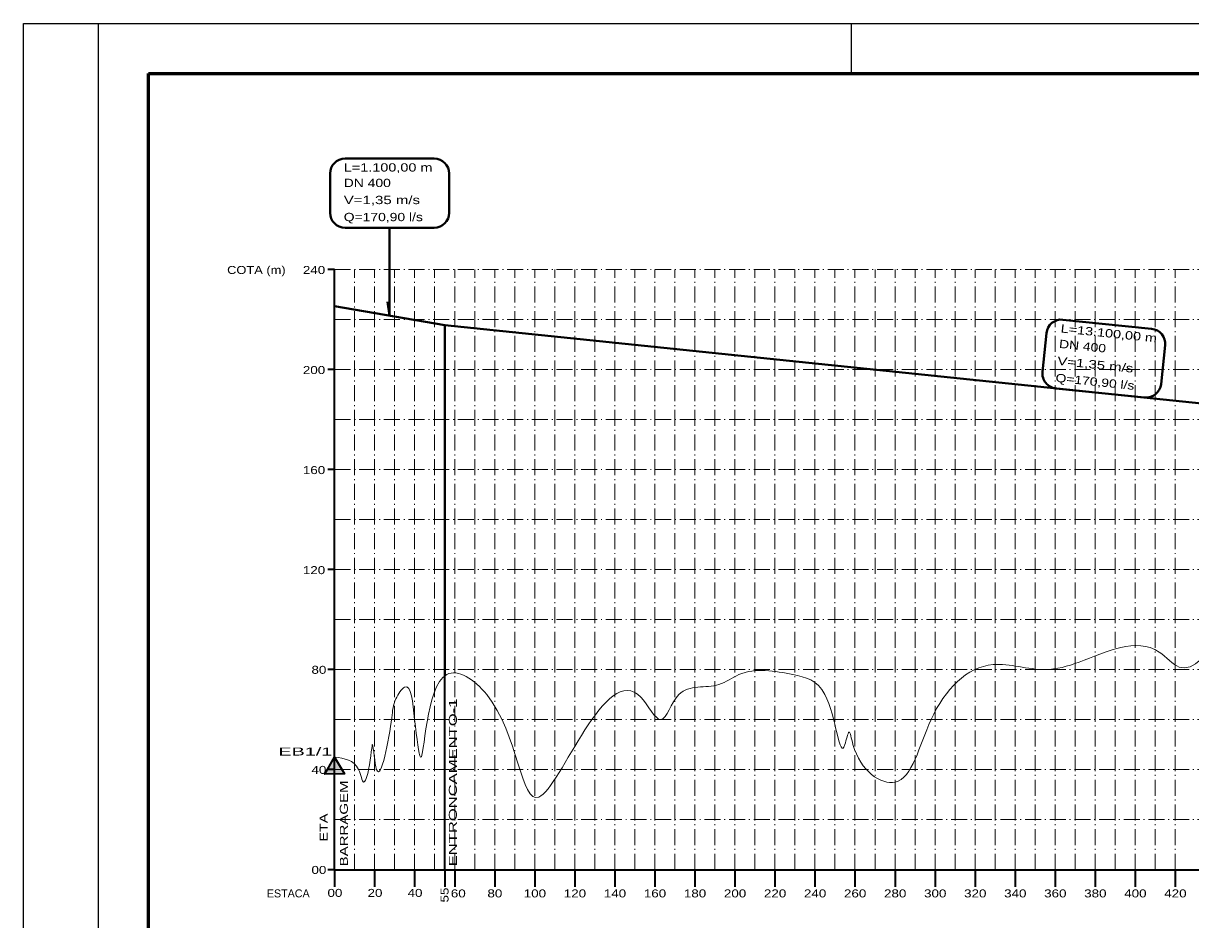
# Model space of a CAD drawing. Extents: x -4 to 42046, y -3 to 29697.
# Drawn here: x -4 to 11660, y 20739 to 29697 of the extents above; entities that cross this region are included whole.
import ezdxf
from ezdxf.enums import TextEntityAlignment as Align

# ---------------------------------------------------------------- set-up
doc = ezdxf.new("R2010")
doc.units = 0
doc.header["$LTSCALE"] = 32
doc.linetypes.add('DOT_DASHED', pattern=[7.7, 5, -1.2, 0.3, -1.2])
for name, color, linetype, lineweight in [('1', 7, 'DOT_DASHED', 13), ('24', 7, 'Continuous', 35), ('55', 7, 'Continuous', 13), ('62', 7, 'Continuous', 13), ('63', 7, 'Continuous', 25), ('9', 7, 'Continuous', 40)]:
    doc.layers.add(name, color=color, linetype=linetype, lineweight=lineweight)

msp = doc.modelspace()

# ---------------------------------------------------------------- hatches: boundary and pattern name
at = {"layer": '62'}
msp.add_hatch(color=256, dxfattribs=at).paths.add_polyline_path([(3106.23, 22363.2), (3204.89, 22194.75), (3009.68, 22193.54)])

# ---------------------------------------------------------------- linework, layer by layer
at = {"layer": '1'}
for p, q in [((3105.77, 27238.44), (32905.77, 27238.44)), ((3305.77, 21238.44), (3305.77, 27238.44)), ((3505.77, 21238.44), (3505.77, 27238.44)), ((3705.77, 21238.44), (3705.77, 27238.44)), ((3905.77, 21238.44), (3905.77, 27238.44)), ((4105.77, 21238.44), (4105.77, 27238.44)), ((4305.77, 21238.44), (4305.77, 27238.44)), ((4505.77, 21238.44), (4505.77, 27238.44)), ((4705.77, 21238.44), (4705.77, 27238.44)), ((4905.77, 21238.44), (4905.77, 27238.44)), ((5105.77, 21238.44), (5105.77, 27238.44)), ((5305.77, 21238.44), (5305.77, 27238.44)), ((5505.77, 21238.44), (5505.77, 27238.44)), ((5705.77, 21238.44), (5705.77, 27238.44)), ((5905.77, 21238.44), (5905.77, 27238.44)), ((6105.77, 21238.44), (6105.77, 27238.44)), ((6305.77, 21238.44), (6305.77, 27238.44)), ((6505.77, 21238.44), (6505.77, 27238.44)), ((6705.77, 21238.44), (6705.77, 27238.44)), ((6905.77, 21238.44), (6905.77, 27238.44)), ((7105.77, 21238.44), (7105.77, 27238.44)), ((7305.77, 21238.44), (7305.77, 27238.44)), ((7505.77, 21238.44), (7505.77, 27238.44)), ((7705.77, 21238.44), (7705.77, 27238.44)), ((7905.77, 21238.44), (7905.77, 27238.44)), ((8105.77, 21238.44), (8105.77, 27238.44)), ((8305.77, 21238.44), (8305.77, 27238.44)), ((8505.77, 21238.44), (8505.77, 27238.44)), ((8705.77, 21238.44), (8705.77, 27238.44)), ((8905.77, 21238.44), (8905.77, 27238.44)), ((9105.77, 21238.44), (9105.77, 27238.44)), ((9305.77, 21238.44), (9305.77, 27238.44)), ((9505.77, 21238.44), (9505.77, 27238.44)), ((9705.77, 21238.44), (9705.77, 27238.44)), ((9905.77, 21238.44), (9905.77, 27238.44)), ((10105.77, 21238.44), (10105.77, 27238.44)), ((10305.77, 21238.44), (10305.77, 27238.44)), ((10505.77, 21238.44), (10505.77, 27238.44)), ((10705.77, 21238.44), (10705.77, 27238.44)), ((10905.77, 21238.44), (10905.77, 27238.44)), ((11105.77, 21238.44), (11105.77, 27238.44)), ((11305.77, 21238.44), (11305.77, 27238.44)), ((11505.77, 21238.44), (11505.77, 27238.44)), ((3105.77, 26738.44), (32905.77, 26738.44)), ((3105.77, 26238.44), (32905.77, 26238.44)), ((3105.77, 25738.44), (32905.77, 25738.44)), ((3105.77, 25238.44), (32905.77, 25238.44)), ((3105.77, 24738.44), (32905.77, 24738.44)), ((3105.77, 24238.44), (32905.77, 24238.44)), ((3105.77, 23738.44), (32905.77, 23738.44)), ((3305.77, 21238.44), (3305.77, 23389.71)), ((3505.77, 21238.44), (3505.77, 23389.71)), ((3705.77, 21238.44), (3705.77, 23389.71)), ((3905.77, 21238.44), (3905.77, 23389.71)), ((4105.77, 21238.44), (4105.77, 23389.71)), ((4305.77, 21238.44), (4305.77, 23389.71)), ((3105.77, 23238.44), (4416.67, 23238.44)), ((3105.77, 23238.44), (32905.77, 23238.44)), ((3105.77, 22738.44), (4416.67, 22738.44)), ((3105.77, 22738.44), (32905.77, 22738.44)), ((3105.77, 22238.44), (4416.67, 22238.44)), ((3105.77, 22238.44), (32905.77, 22238.44)), ((3105.77, 21738.44), (4416.67, 21738.44)), ((3105.77, 21738.44), (32905.77, 21738.44))]:
    msp.add_line(p, q, dxfattribs=at)
at = {"layer": '55'}
msp.add_spline([(3105.77, 22363.44), (3345.77, 22238.44), (3395.77, 22113.44), (3445.77, 22238.44), (3485.77, 22488.44), (3525.77, 22238.44), (3676.64, 22756.56), (3717.19, 22944.93), (3805.77, 23063.44), (3905.77, 22738.44), (3965.77, 22363.44), (4225.77, 23188.44), (4625.77, 22988.44), (5145.77, 21963.44), (6165.77, 22963.44), (6365.77, 22738.44), (6545.77, 22988.44), (6945.77, 23088.44), (7145.77, 23188.44), (7685.77, 23188.44), (8005.77, 22988.44), (8205.77, 22488.44), (8245.77, 22613.44), (8285.77, 22488.44), (8705.77, 22113.44), (9065.77, 22738.44), (9685.77, 23288.44), (10205.77, 23238.44), (10545.77, 23313.44), (11345.77, 23413.44), (11545.77, 23263.44), (12365.77, 23988.44), (12705.77, 23613.44), (12805.77, 23563.44), (13605.77, 23863.44), (13845.77, 23738.44), (13905.77, 23663.44), (14265.77, 24038.44), (14465.77, 24088.44), (14965.77, 23738.44), (15205.77, 23988.44), (15365.77, 23738.44), (15665.77, 23488.44), (15885.77, 23813.44), (16285.77, 23363.44), (16785.77, 22488.44), (16825.77, 22363.44), (16985.77, 22863.44), (17065.77, 22738.44), (17225.77, 22588.44), (17685.77, 22288.44), (17925.77, 22338.44), (18085.77, 22288.44), (18185.77, 22488.44), (18285.77, 22388.44), (18705.77, 22488.44), (18785.77, 22538.44), (18845.77, 22488.44), (19325.77, 22888.44), (19685.77, 22363.44), (20185.77, 22988.44), (20645.77, 23188.44), (21145.77, 22588.44), (21245.77, 22738.44), (21425.77, 22563.44), (21525.77, 22613.44), (21645.77, 22738.44), (21745.77, 22363.44), (21845.77, 22688.44), (22085.77, 22613.44), (22445.77, 23238.44), (23265.77, 23663.44), (23585.77, 23313.44), (23905.77, 23563.44), (24365.77, 23413.44), (24725.77, 23613.44), (25545.77, 23113.44), (26045.77, 23613.44), (27245.77, 23988.44), (27705.77, 23563.44), (27905.77, 23738.44), (28085.77, 23588.44), (28605.77, 24113.44), (29205.77, 23638.44), (29325.77, 23738.44), (29405.77, 23563.44)], degree=3, dxfattribs=at)
at = {"layer": '62', "lineweight": 35}
for p, q in [((3105.77, 27238.44), (3037.5, 27238.44)), ((3101.57, 27238.44), (3105.77, 27238.44)), ((3105.77, 21238.44), (3105.77, 27238.44)), ((3101.57, 26988.44), (3105.77, 26988.44)), ((3101.57, 26738.44), (3105.77, 26738.44)), ((3101.57, 26488.44), (3105.77, 26488.44)), ((3105.77, 26238.44), (3037.5, 26238.44)), ((3101.57, 26238.44), (3105.77, 26238.44)), ((3101.57, 25988.44), (3105.77, 25988.44)), ((3101.57, 25738.44), (3105.77, 25738.44)), ((3101.57, 25488.44), (3105.77, 25488.44)), ((3105.77, 25238.44), (3037.5, 25238.44)), ((3101.57, 25238.44), (3105.77, 25238.44)), ((3101.57, 24988.44), (3105.77, 24988.44)), ((3101.57, 24738.44), (3105.77, 24738.44)), ((3101.57, 24488.44), (3105.77, 24488.44)), ((3105.77, 24238.44), (3037.5, 24238.44)), ((3101.57, 24238.44), (3105.77, 24238.44)), ((3101.57, 23988.44), (3105.77, 23988.44)), ((3101.57, 23738.44), (3105.77, 23738.44)), ((3101.57, 23488.44), (3105.77, 23488.44)), ((3105.77, 21238.44), (3105.77, 23389.71)), ((3105.77, 23238.44), (3037.5, 23238.44)), ((3105.77, 23238.44), (3037.5, 23238.44)), ((3101.57, 23238.44), (3105.77, 23238.44)), ((3101.57, 23238.44), (3105.77, 23238.44)), ((4205.77, 21238.44), (4205.77, 23188.44)), ((3101.57, 22988.44), (3105.77, 22988.44)), ((3101.57, 22988.44), (3105.77, 22988.44)), ((3101.57, 22738.44), (3105.77, 22738.44)), ((3101.57, 22738.44), (3105.77, 22738.44)), ((3101.57, 22488.44), (3105.77, 22488.44)), ((3101.57, 22488.44), (3105.77, 22488.44)), ((3105.77, 22238.44), (3037.5, 22238.44)), ((3101.57, 22238.44), (3105.77, 22238.44)), ((3101.57, 22238.44), (3105.77, 22238.44)), ((3101.57, 21988.44), (3105.77, 21988.44)), ((3101.57, 21988.44), (3105.77, 21988.44)), ((3101.57, 21738.44), (3105.77, 21738.44)), ((3101.57, 21738.44), (3105.77, 21738.44)), ((3101.57, 21488.44), (3105.77, 21488.44)), ((3101.57, 21488.44), (3105.77, 21488.44)), ((3105.77, 21238.44), (3037.5, 21238.44)), ((3105.77, 21238.44), (3037.5, 21238.44)), ((3105.77, 21238.44), (3105.77, 21067.76)), ((3105.77, 21238.44), (3105.77, 21067.76)), ((3105.77, 21238.44), (4416.67, 21238.44)), ((3505.77, 21238.44), (3505.77, 21067.76)), ((3505.77, 21238.44), (3505.77, 21067.76)), ((3905.77, 21238.44), (3905.77, 21067.76)), ((3905.77, 21238.44), (3905.77, 21067.76)), ((4205.77, 21238.44), (4205.77, 21067.76)), ((4205.77, 21238.44), (4205.77, 21067.76)), ((4305.77, 21238.44), (4305.77, 21067.76)), ((4305.77, 21238.44), (4305.77, 21067.76)), ((4705.77, 21238.44), (4705.77, 21067.76)), ((5105.77, 21238.44), (5105.77, 21067.76)), ((5505.77, 21238.44), (5505.77, 21067.76)), ((5905.77, 21238.44), (5905.77, 21067.76)), ((6305.77, 21238.44), (6305.77, 21067.76)), ((6705.77, 21238.44), (6705.77, 21067.76)), ((7105.77, 21238.44), (7105.77, 21067.76)), ((7505.77, 21238.44), (7505.77, 21067.76)), ((7905.77, 21238.44), (7905.77, 21067.76)), ((8305.77, 21238.44), (8305.77, 21067.76)), ((8705.77, 21238.44), (8705.77, 21067.76)), ((9105.77, 21238.44), (9105.77, 21067.76)), ((9505.77, 21238.44), (9505.77, 21067.76)), ((9905.77, 21238.44), (9905.77, 21067.76)), ((10305.77, 21238.44), (10305.77, 21067.76)), ((10705.77, 21238.44), (10705.77, 21067.76)), ((11105.77, 21238.44), (11105.77, 21067.76)), ((11505.77, 21238.44), (11505.77, 21067.76))]:
    msp.add_line(p, q, dxfattribs=at)
at = {"layer": '62'}
for p, q in [((3101.57, 27188.44), (3105.77, 27188.44)), ((3101.57, 27138.44), (3105.77, 27138.44)), ((3101.57, 27088.44), (3105.77, 27088.44)), ((3101.57, 27038.44), (3105.77, 27038.44)), ((3101.57, 26938.44), (3105.77, 26938.44)), ((3101.57, 26888.44), (3105.77, 26888.44)), ((3101.57, 26838.44), (3105.77, 26838.44)), ((3101.57, 26788.44), (3105.77, 26788.44)), ((3101.57, 26688.44), (3105.77, 26688.44)), ((3101.57, 26638.44), (3105.77, 26638.44)), ((3101.57, 26588.44), (3105.77, 26588.44)), ((3101.57, 26538.44), (3105.77, 26538.44)), ((3101.57, 26438.44), (3105.77, 26438.44)), ((3101.57, 26388.44), (3105.77, 26388.44)), ((3101.57, 26338.44), (3105.77, 26338.44)), ((3101.57, 26288.44), (3105.77, 26288.44)), ((3101.57, 26188.44), (3105.77, 26188.44)), ((3101.57, 26138.44), (3105.77, 26138.44)), ((3101.57, 26088.44), (3105.77, 26088.44)), ((3101.57, 26038.44), (3105.77, 26038.44)), ((3101.57, 25938.44), (3105.77, 25938.44)), ((3101.57, 25888.44), (3105.77, 25888.44)), ((3101.57, 25838.44), (3105.77, 25838.44)), ((3101.57, 25788.44), (3105.77, 25788.44)), ((3101.57, 25688.44), (3105.77, 25688.44)), ((3101.57, 25638.44), (3105.77, 25638.44)), ((3101.57, 25588.44), (3105.77, 25588.44)), ((3101.57, 25538.44), (3105.77, 25538.44)), ((3101.57, 25438.44), (3105.77, 25438.44)), ((3101.57, 25388.44), (3105.77, 25388.44)), ((3101.57, 25338.44), (3105.77, 25338.44)), ((3101.57, 25288.44), (3105.77, 25288.44)), ((3101.57, 25188.44), (3105.77, 25188.44)), ((3101.57, 25138.44), (3105.77, 25138.44)), ((3101.57, 25088.44), (3105.77, 25088.44)), ((3101.57, 25038.44), (3105.77, 25038.44)), ((3101.57, 24938.44), (3105.77, 24938.44)), ((3101.57, 24888.44), (3105.77, 24888.44)), ((3101.57, 24838.44), (3105.77, 24838.44)), ((3101.57, 24788.44), (3105.77, 24788.44)), ((3101.57, 24688.44), (3105.77, 24688.44)), ((3101.57, 24638.44), (3105.77, 24638.44)), ((3101.57, 24588.44), (3105.77, 24588.44)), ((3101.57, 24538.44), (3105.77, 24538.44)), ((3101.57, 24438.44), (3105.77, 24438.44)), ((3101.57, 24388.44), (3105.77, 24388.44)), ((3101.57, 24338.44), (3105.77, 24338.44)), ((3101.57, 24288.44), (3105.77, 24288.44)), ((3101.57, 24188.44), (3105.77, 24188.44)), ((3101.57, 24138.44), (3105.77, 24138.44)), ((3101.57, 24088.44), (3105.77, 24088.44)), ((3101.57, 24038.44), (3105.77, 24038.44)), ((3101.57, 23938.44), (3105.77, 23938.44)), ((3101.57, 23888.44), (3105.77, 23888.44)), ((3101.57, 23838.44), (3105.77, 23838.44)), ((3101.57, 23788.44), (3105.77, 23788.44)), ((3101.57, 23688.44), (3105.77, 23688.44)), ((3101.57, 23638.44), (3105.77, 23638.44)), ((3101.57, 23588.44), (3105.77, 23588.44)), ((3101.57, 23538.44), (3105.77, 23538.44)), ((3101.57, 23438.44), (3105.77, 23438.44)), ((3101.57, 23388.44), (3105.77, 23388.44)), ((3101.57, 23388.44), (3105.77, 23388.44)), ((3101.57, 23338.44), (3105.77, 23338.44)), ((3101.57, 23338.44), (3105.77, 23338.44)), ((3101.57, 23288.44), (3105.77, 23288.44)), ((3101.57, 23288.44), (3105.77, 23288.44)), ((3101.57, 23188.44), (3105.77, 23188.44)), ((3101.57, 23188.44), (3105.77, 23188.44)), ((3101.57, 23138.44), (3105.77, 23138.44)), ((3101.57, 23138.44), (3105.77, 23138.44)), ((3101.57, 23088.44), (3105.77, 23088.44)), ((3101.57, 23088.44), (3105.77, 23088.44)), ((3101.57, 23038.44), (3105.77, 23038.44)), ((3101.57, 23038.44), (3105.77, 23038.44)), ((3101.57, 22938.44), (3105.77, 22938.44)), ((3101.57, 22938.44), (3105.77, 22938.44)), ((3101.57, 22888.44), (3105.77, 22888.44)), ((3101.57, 22888.44), (3105.77, 22888.44)), ((3101.57, 22838.44), (3105.77, 22838.44)), ((3101.57, 22838.44), (3105.77, 22838.44)), ((3101.57, 22788.44), (3105.77, 22788.44)), ((3101.57, 22788.44), (3105.77, 22788.44)), ((3101.57, 22688.44), (3105.77, 22688.44)), ((3101.57, 22688.44), (3105.77, 22688.44)), ((3101.57, 22638.44), (3105.77, 22638.44)), ((3101.57, 22638.44), (3105.77, 22638.44)), ((3101.57, 22588.44), (3105.77, 22588.44)), ((3101.57, 22588.44), (3105.77, 22588.44)), ((3101.57, 22538.44), (3105.77, 22538.44)), ((3101.57, 22538.44), (3105.77, 22538.44)), ((3101.57, 22438.44), (3105.77, 22438.44)), ((3101.57, 22438.44), (3105.77, 22438.44)), ((3101.57, 22388.44), (3105.77, 22388.44)), ((3101.57, 22388.44), (3105.77, 22388.44)), ((3101.57, 22338.44), (3105.77, 22338.44)), ((3101.57, 22338.44), (3105.77, 22338.44)), ((3101.57, 22288.44), (3105.77, 22288.44)), ((3101.57, 22288.44), (3105.77, 22288.44)), ((3101.57, 22188.44), (3105.77, 22188.44)), ((3101.57, 22188.44), (3105.77, 22188.44)), ((3101.57, 22138.44), (3105.77, 22138.44)), ((3101.57, 22138.44), (3105.77, 22138.44)), ((3101.57, 22088.44), (3105.77, 22088.44)), ((3101.57, 22088.44), (3105.77, 22088.44)), ((3101.57, 22038.44), (3105.77, 22038.44)), ((3101.57, 22038.44), (3105.77, 22038.44)), ((3101.57, 21938.44), (3105.77, 21938.44)), ((3101.57, 21938.44), (3105.77, 21938.44)), ((3101.57, 21888.44), (3105.77, 21888.44)), ((3101.57, 21888.44), (3105.77, 21888.44)), ((3101.57, 21838.44), (3105.77, 21838.44)), ((3101.57, 21838.44), (3105.77, 21838.44)), ((3101.57, 21788.44), (3105.77, 21788.44)), ((3101.57, 21788.44), (3105.77, 21788.44)), ((3101.57, 21688.44), (3105.77, 21688.44)), ((3101.57, 21688.44), (3105.77, 21688.44)), ((3101.57, 21638.44), (3105.77, 21638.44)), ((3101.57, 21638.44), (3105.77, 21638.44)), ((3101.57, 21588.44), (3105.77, 21588.44)), ((3101.57, 21588.44), (3105.77, 21588.44)), ((3101.57, 21538.44), (3105.77, 21538.44)), ((3101.57, 21538.44), (3105.77, 21538.44)), ((3101.57, 21438.44), (3105.77, 21438.44)), ((3101.57, 21438.44), (3105.77, 21438.44)), ((3101.57, 21388.44), (3105.77, 21388.44)), ((3101.57, 21388.44), (3105.77, 21388.44)), ((3101.57, 21338.44), (3105.77, 21338.44)), ((3101.57, 21338.44), (3105.77, 21338.44)), ((3101.57, 21288.44), (3105.77, 21288.44)), ((3101.57, 21288.44), (3105.77, 21288.44))]:
    msp.add_line(p, q, dxfattribs=at)
at = {"layer": '62', "lineweight": 35}
msp.add_lwpolyline([(3106.23, 22363.2), (3204.89, 22194.75), (3009.68, 22193.54)], close=True, dxfattribs=at)
for points in [[(3101.57, 22238.44), (3105.77, 22238.44), (3037.5, 22238.44)], [(3105.77, 21238.44), (10105.77, 21238.44), (29905.77, 21238.44)]]:
    msp.add_lwpolyline(points, dxfattribs=at)
at = {"layer": '63'}
for p, q in [((-4.21, 29697.03), (42045.8, 29697.03)), ((-4.21, -2.97), (-4.21, 29697.03)), ((745.8, 14847.03), (745.8, 29697.03)), ((8270.8, 29197.03), (8270.8, 29697.03))]:
    msp.add_line(p, q, dxfattribs=at)
at = {"layer": '63', "lineweight": 60}
for points in [[(1245.8, 29197.03), (41545.8, 29197.03), (41545.8, 497.03), (32795.79, 497.03)], [(23554.57, 497.03), (1245.8, 497.03), (1245.8, 29197.03)]]:
    msp.add_lwpolyline(points, dxfattribs=at)
at = {"layer": '9'}
for p, q in [((3210.35, 28344.84), (4101.2, 28344.84)), ((3060.35, 28194.84), (3060.35, 27804.57)), ((4251.2, 28194.84), (4251.2, 27804.57)), ((3210.35, 27654.57), (4101.2, 27654.57)), ((10383.87, 26735.44), (11269.97, 26643.61)), ((4205.77, 23188.44), (4205.77, 26681.69)), ((10219.2, 26601.7), (10178.98, 26213.51)), ((11403.71, 26478.95), (11363.49, 26090.77)), ((10312.72, 26048.85), (11198.82, 25957.03))]:
    msp.add_line(p, q, dxfattribs=at)
for points in [[(3634.98, 26912.06), (3655.77, 26776.19), (3655.77, 27654.57)], [(3105.77, 26870.69), (4205.77, 26681.69), (17305.77, 25324.19), (29905.77, 24238.44), (29905.77, 25414.4), (32905.77, 24663.44)]]:
    msp.add_lwpolyline(points, dxfattribs=at)
for centre, start, end in [((3210.35, 28194.84), 90, 180), ((4101.2, 28194.84), 0, 90), ((3210.35, 27804.57), 180, 270), ((4101.2, 27804.57), 270, 0), ((10368.4, 26586.24), 84.08379, 174.08379), ((11254.51, 26494.41), 354.08379, 84.08379), ((10328.18, 26198.05), 174.08379, 264.08379), ((11214.29, 26106.23), 264.08379, 354.08379)]:
    msp.add_arc(centre, 150, start, end, dxfattribs=at)

# ---------------------------------------------------------------- texts
at = {"layer": '24'}
for s, width, p in [('COTA (m)', 1.2, (2616.74, 27192.04)), ('240', 1.25, (3011.93, 27192.04)), ('200', 1.25, (3011.93, 26192.04)), ('160', 1.25, (3011.93, 25192.04)), ('120', 1.25, (3011.93, 24192.04)), ('80', 1.25, (3023.55, 23195.91)), ('40', 1.25, (3023.55, 22195.91)), ('00', 1.25, (3023.55, 21195.91))]:
    msp.add_text(s, height=80, dxfattribs=dict(at, width=width)).set_placement(p, align=Align.RIGHT)
for s, width, p in [('ENTRONCAMENTO-1', 1.55, (4327.66, 21272.06)), ('BARRAGEM', 1.4, (3238.39, 21272.06)), ('ETA', 1.35, (3036.28, 21518.43))]:
    msp.add_text(s, height=80, rotation=90, dxfattribs=dict(at, width=width)).set_placement(p)
at = {"layer": '24', "width": 1.85}
msp.add_text('EB1/1', height=80, dxfattribs=at).set_placement((2544.01, 22379.52))
at = {"layer": '24'}
msp.add_text('ESTACA', height=80, dxfattribs=at).set_placement((2642.65, 20961.24), align=Align.CENTER)
at = {"layer": '24', "width": 1.25}
for s, p in [('00', (3109.27, 20966.16)), ('20', (3509.27, 20966.16)), ('40', (3909.27, 20966.16)), ('60', (4341.71, 20961.24)), ('80', (4707.4, 20961.24)), ('100', (5107.4, 20961.24)), ('120', (5507.4, 20961.24)), ('140', (5907.4, 20961.24)), ('160', (6307.4, 20961.24)), ('180', (6707.4, 20961.24)), ('200', (7107.4, 20961.24)), ('220', (7507.4, 20961.24)), ('240', (7907.4, 20961.24)), ('260', (8307.4, 20961.24)), ('280', (8707.4, 20961.24)), ('300', (9107.4, 20961.24)), ('320', (9507.4, 20961.24)), ('340', (9907.4, 20961.24)), ('360', (10307.4, 20961.24)), ('380', (10707.4, 20961.24)), ('400', (11107.4, 20961.24)), ('420', (11507.4, 20961.24))]:
    msp.add_text(s, height=80, dxfattribs=at).set_placement(p, align=Align.CENTER)
msp.add_text('55', height=80, rotation=90, dxfattribs=at).set_placement((4244.17, 20985.24), align=Align.CENTER)
at = {"layer": '9'}
for s, width, p in [('L=1.100,00 m', 1.3, (3197.47, 28215.37)), ('DN 400', 1.25, (3197.47, 28060.88)), ('V=1,35 m/s', 1.35, (3197.47, 27890.29)), ('Q=170,90 l/s', 1.25, (3197.47, 27719.7))]:
    msp.add_text(s, height=82.98, dxfattribs=dict(at, width=width)).set_placement(p)
for s, width, p in [('L=13.100,00 m', 1.3, (10357.71, 26607.99)), ('DN 400', 1.25, (10341.79, 26454.32)), ('V=1,35 m/s', 1.35, (10324.2, 26284.64)), ('Q=170,90 l/s', 1.25, (10306.62, 26114.96))]:
    msp.add_text(s, height=82.98, rotation=354.084, dxfattribs=dict(at, width=width)).set_placement(p)

doc.saveas('drawing.dxf')
